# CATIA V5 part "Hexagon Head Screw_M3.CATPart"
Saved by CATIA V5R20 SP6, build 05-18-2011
Part number: Hexagon_Head_Screw_M3
Bounding box of the stored display mesh (mm): x -2.741 to 2.741, y -2.75 to 2.75, z -16 to 0
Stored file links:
  E:\#01 CATIA Lecture Materials\#06 DMU\#03 DMU Page01 KIN EX03\Hexagon Head Screw_M3.CATPart
  F:\RCCAR\Project(MJ)\hexagon head screw.xls
  C:\Program Files\Dassault Systemes\B20\win_b64\startup\materials\Catalog.CATMaterial
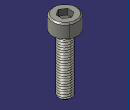
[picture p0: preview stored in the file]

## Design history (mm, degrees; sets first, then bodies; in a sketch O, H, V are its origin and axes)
External parameters (linked from other documents)
  External.d_Head = 5.5 mm
  External.K_Head_Height = 3 mm
  External.ds_Body = 3 mm
  External.Pitch = 0.5 mm
  External.lead = 13 mm
  External.v = 0.3 mm
  External.k = 0.6 mm
  External.t = 1.3 mm
  External.s = 2.56 mm
  `External.Bolt Type` = "M3"
Body1 (main body)
  Body2
    Sketch1 on yz-plane, origin (0, 0, 0), H (0, 1, 0), V (0, 0, 1)
      line L1 (2.75, -3) -> (2.75, 0)
      point P2 (2.75, 0)
      line L2 (2.75, 0) -> (0, 0)
      construction line L3 (0, 50.6222) -> (0, -71.272)
      point P3 (0, 50.6222)
      line L4 (2.75, -3) -> (0, -3)
      point P5 (0, -3)
      axis line L5 (0, 17.6953) -> (0, -27.6198)
      point P6 (0, 17.6953)
      reference intersected line E1 through (0, -3) direction (-1, 0) from Plane1
      distance L1 L3 = 2.75 {= External.d_Head /2}
      coincidence: P2 H, P3 V, P6 L3, E1 L4, P5 V
      vertical: L1 V, L3 V, L5 V
      horizontal: L2 H, L4 H
    Shaft1: profile Sketch1, axis Sketch1.L5, angle 360
    Chamfer1: length 0.3 {= External.v}, angle 45, on edge [face of Shaft1 from Sketch1.L2 | face of Shaft1 from Sketch1.L1]
    Body3
      Sketch2 on face of Shaft1 from Sketch1.L4, origin (0, 0, -3), H (1, 0, 0), V (0, -1, 0)
        circle A1 centre (0, 0) radius 1.5
        radius A1 = 1.5 {= External.ds_Body /2}
      Pad1: profile Sketch2, direction (0, 0, -1), length 13 {= External.lead}
      Chamfer2: length 0.6 {= External.k}, angle 45, on edge [face of Pad1 from Sketch2.A1 | end face of Pad1]
      Split1: SplitPlane Join1
    Assemble1: tool Body3
  Assemble2: tool Body2
  Body4
    Sketch3 on xy-plane, origin (0, 0, 0), H (1, 0, 0), V (0, 1, 0)
      point P1 (0, 0)
      point P2 (1.28, -0.739)
      point P3 (1.28, 0.739)
      point P4 (0, 1.478)
      point P5 (-1.28, 0.739)
      point P6 (-1.28, -0.739)
      point P7 (0, -1.478)
      point P8 (1.28, 0)
      line L1 (1.28, -0.739) -> (1.28, 0.739)
      line L2 (1.28, 0.739) -> (0, 1.478)
      line L3 (0, 1.478) -> (-1.28, 0.739)
      line L4 (-1.28, 0.739) -> (-1.28, -0.739)
      line L5 (-1.28, -0.739) -> (0, -1.478)
      line L6 (0, -1.478) -> (1.28, -0.739)
      construction line L7 (0, 0) -> (1.28, 0)
      construction circle A1 centre (0, 0) radius 1.478
      construction arc A2 centre (-1.28, -0.739) radius 1.478 from (-1.28, 0.739) to (0, -1.478) cw
      construction arc A3 centre (1.28, 0.739) radius 1.478 from (0, 1.478) to (1.28, -0.739) ccw
      distance L1 L4 = 2.56 {= External.s}
      coincidence: P1 V, A1 P2, A1 P3, A1 P4, A1 P5, A1 P6, A1 P7, A2 P1, A3 P1, H L7
      horizontal: L7 H
      midpoint: P8 L1
    Pocket1: profile Sketch3, direction (0, 0, -1), length 1.3 {= External.t}
    Set1 "Reference Data"
      Point1 "Center Point": (0, 0, 0)
      Plane1: type Offset, RefPlane xy-plane, Offset 3 {= External.K_Head_Height}, reversed
      Set2 "Helix Body"
        Helix1: Direction Z axis, RefPoint {point type Coord, X 0, Y 1.5 {= External.ds_Body /2}, Z -2 {= -External.K_Head_Height +1mm}}, Pitch 0.5 {= External.Pitch}, Height 23 {= External.lead +10mm}, TaperAngle 0
        Sweep1: type Segment, GuideCrv Helix1, Length1 0.5 {= External.Pitch}, Length2 0.2, Angle 60, DraftDirection xy-plane
        Sweep2: type Segment, GuideCrv Helix1, Length1 0.5 {= External.Pitch}, Length2 0.2, Angle 60, DraftDirection xy-plane
        Trim1: Trimmed (Sweep1; Sweep2)
        Split2: ToCut Trim1, Cutting Plane1
        Fill1: Boundary {boundary Boundary edge of Split2, Support Split2}
        Join1: Elements (Split2; Fill1)
  Remove1: tool Body4
Relations
  rule:
    if `External.Bolt Type` =="M1.6"
    	{
    		External.d_Head =3.14mm
    		External.K_Head_Height =1.6mm
    		External.ds_Body =1.6mm
    		External.Pitch =0.35mm
    		External.lead =10mm
    		External.v=0.16mm
    		External.k =0.16mm
    		External.t =0.7mm
    		External.s =1.545mm
    	}
    else if `External.Bolt Type` =="M2"
    	{
    		External.d_Head =3.98mm
    		External.K_Head_Height =2mm
    		External.ds_Body =2mm
    		External.Pitch =0.4mm
    		External.lead =10mm
    		External.v=0.2mm
    		External.k =0.25mm
    		External.t =1mm
    		External.s =1.545mm
    	}
    else if `External.Bolt Type` =="M2.5"
    	{
    		External.d_Head =4.68mm
    		External.K_Head_Height =2.5mm
    		External.ds_Body =2.5mm
    		External.Pitch =0.45mm
    		External.lead =10mm
    		External.v=0.25mm
    		External.k =0.4mm
    		External.t =1.1mm
    		External.s=2.045mm
    	}
    else if `External.Bolt Type` =="M3"
    	{
    		External.d_Head =5.5mm
    		External.K_Head_Height =3mm
    		External.ds_Body =3mm
    		External.Pitch =0.5mm
    		External.lead =13mm
    		External.v=0.3mm
    		External.k =0.6mm
    		External.t =1.3mm
    		External.s=2.56mm
    	}
    else if `External.Bolt Type` =="M3.5"
    	{
    		External.d_Head =6.38mm
    		External.K_Head_Height =3.5mm
    		External.ds_Body =3.5mm
    		External.Pitch =0.55mm
    		External.lead =15mm
    		External.v=0.35mm
    		External.k =0.75mm
    		External.t =1.5mm
    		External.s=3.06mm
    	}
    else if `External.Bolt Type` =="M4"
    	{
    		External.d_Head =7.38mm
    		External.K_Head_Height =4mm
    		External.ds_Body =4mm
    		External.Pitch =0.6mm
    		External.lead =20mm
    		External.v=0.4mm
    		External.k =0.95mm
    		External.t =2mm
    		External.s=3.575mm
    	}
